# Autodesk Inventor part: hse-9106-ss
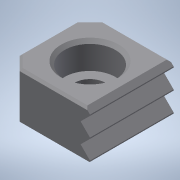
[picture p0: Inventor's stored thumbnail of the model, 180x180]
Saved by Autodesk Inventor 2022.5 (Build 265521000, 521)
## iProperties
Created: 2016-12
Part Number: hse-9106-ss
Material: 一般
Document SubType Name: Modeling
Designer: imaocorp
Density: 1 g/cm^3
Appearance: 既定
Author: imaocorp
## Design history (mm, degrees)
node "hse-9106-ss.x_t1"
node "hse-9106-ss"
node "Base1"
